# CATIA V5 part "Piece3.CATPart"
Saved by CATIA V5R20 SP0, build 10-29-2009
Part number: Piece3
Bounding box of the stored display mesh (mm): x 0 to 20, y 31.305 to 38.491, z -10.884 to 13.061
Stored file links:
  C:\Users\ASUS\Desktop\Think Motion IAO\Piece3.CATPart
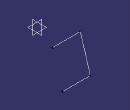
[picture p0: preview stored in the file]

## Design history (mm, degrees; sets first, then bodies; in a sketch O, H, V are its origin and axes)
Body1 (main body)
  Point1 "Point.B": stored without definition
  Line1: type PtDir, RefPoint Point1, Direction yz-plane, Start 0, End 20
  Point2 "Point.C": stored without definition
  Line2: type PtDir, RefPoint Point2, Direction yz-plane, Start 0, End 20
  Point3 "Point.B": stored without definition
  Point4 "Point.C": stored without definition
  Line3: type PtPt, FirstPoint Point3, SecondPoint Point4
